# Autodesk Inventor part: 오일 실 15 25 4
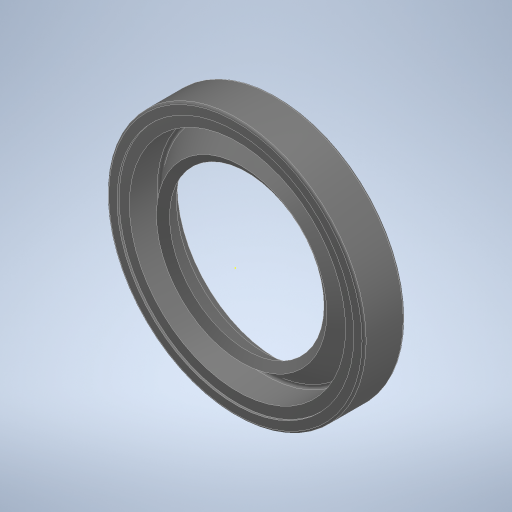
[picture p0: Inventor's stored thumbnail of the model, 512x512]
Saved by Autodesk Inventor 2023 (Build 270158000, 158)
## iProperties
Created: 2025-10
Part Number: 오일 실 15 25 4
Material: 고무
Description: 오일 실 - 비스프링, 조립 GA
Document SubType Name: Modeling
Designer: home
Density: 0.93 g/cm^3
Appearance: 기본값
Author: jhkim
Sending System: Autodesk Inventor 2026
Preprocessor: ST-DEVELOPER v20.1
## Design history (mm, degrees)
sketch "스케치1"
  geometry: 1 further point
  constraints: 1 other
feature "Solid1"
node "솔리드1"
